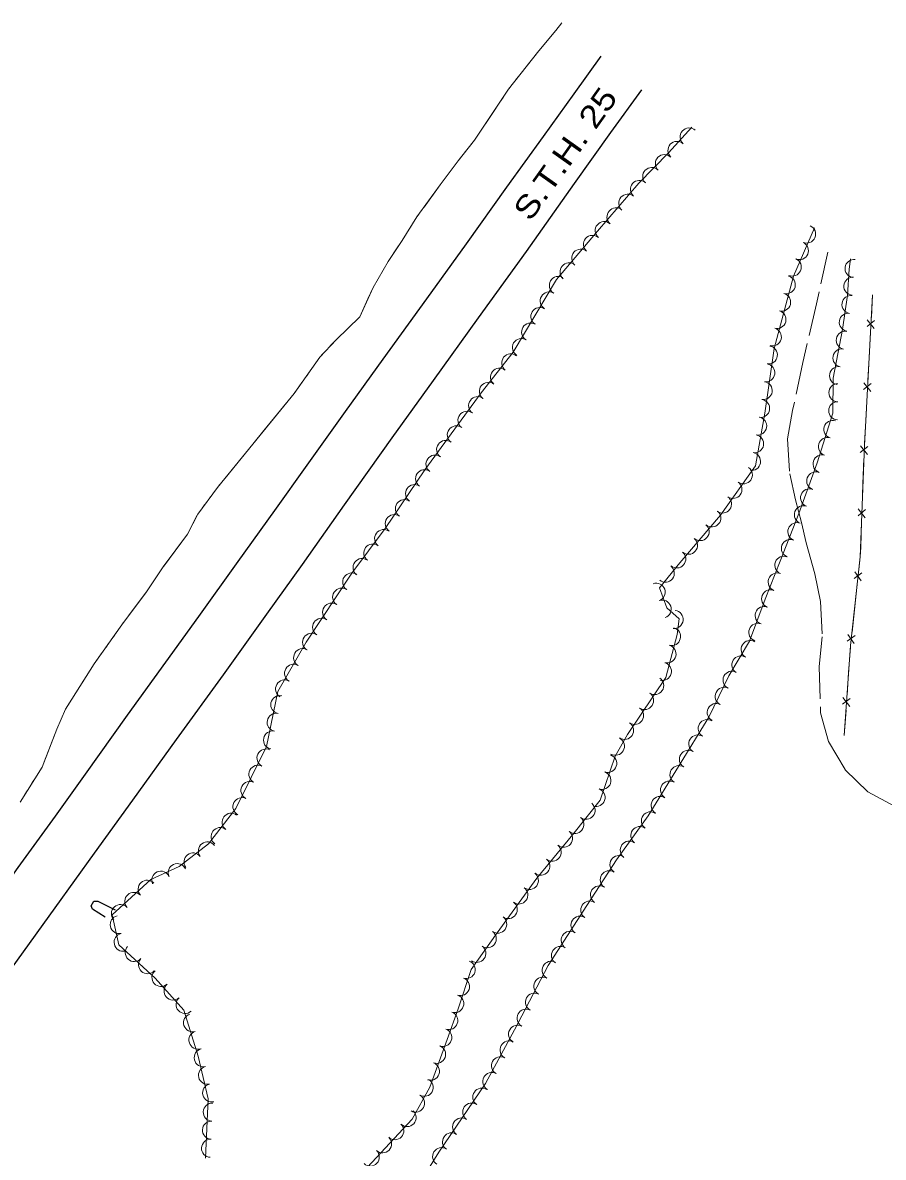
# Model space of a CAD drawing. Extents: x 298761 to 300931, y 48584 to 50968.
# Drawn here: x 300012 to 300394, y 49634 to 50137 of the extents above; entities that cross this region are included whole.
import ezdxf

# ---------------------------------------------------------------- set-up
doc = ezdxf.new("R2010")
doc.units = 0
doc.header["$LTSCALE"] = 2.4
doc.linetypes.add('LONG_DASHED', pattern=[7.5, 6, -1.5])
for name, color, linetype, lineweight in [('11', 7, 'Continuous', 25), ('15', 7, 'Continuous', 13), ('17', 7, 'LONG_DASHED', 13), ('18', 7, 'Continuous', 13), ('19', 7, 'Continuous', 13)]:
    doc.layers.add(name, color=color, linetype=linetype, lineweight=lineweight)

msp = doc.modelspace()

# ---------------------------------------------------------------- linework, layer by layer
at = {"layer": '11'}
for points in [[(299915.873, 49630.321), (299931.973, 49652.924), (299946.639, 49673.137), (299961.48, 49693.774), (299977.848, 49716.32), (299993.395, 49737.881), (300010.454, 49762.179), (300027.109, 49784.923), (300040.39, 49803.549), (300059.076, 49829.713), (300075.951, 49853.169), (300090.619, 49873.467), (300108.059, 49897.84), (300124.331, 49920.482), (300138.8, 49940.607), (300155.789, 49964.508), (300172.496, 49987.622), (300191.823, 50014.425), (300209.423, 50038.876), (300227.388, 50064), (300243.582, 50086.409), (300257.176, 50105.425), (300269.259, 50122.088)], [(299941.753, 49625.456), (299958.193, 49648.483), (299975.851, 49673.327), (299990.952, 49694.469), (300010.158, 49721.046), (300026.858, 49744.237), (300044.29, 49768.502), (300061.337, 49792.04), (300080.812, 49818.961), (300101.569, 49847.571), (300120.862, 49874.589), (300136.668, 49896.558), (300155.344, 49923.099), (300176.493, 49952.718), (300194.769, 49978.148), (300214.8, 50006.036), (300236.015, 50035.498), (300257.333, 50065.558), (300273.546, 50088.222), (300287.176, 50107.164)]]:
    msp.add_lwpolyline(points, dxfattribs=at)
at = {"layer": '15'}
for p, q in [((300389.671, 50016.169), (300389.121, 50006.178)), ((300390.552, 50004.76), (300387.216, 50002.13)), ((300387.312, 50005.11), (300390.356, 50001.201)), ((300388.757, 49999.573), (300388.131, 49988.213)), ((300388.131, 49988.213), (300387.581, 49978.222)), ((300389.012, 49976.804), (300385.676, 49974.174)), ((300385.772, 49977.154), (300388.816, 49973.245)), ((300387.217, 49971.617), (300386.591, 49960.257)), ((300386.591, 49960.257), (300386.041, 49950.265)), ((300387.482, 49948.876), (300384.196, 49946.183)), ((300384.235, 49949.164), (300387.353, 49945.314)), ((300385.785, 49943.656), (300385.374, 49932.286)), ((300385.374, 49932.286), (300385.013, 49922.286)), ((300386.472, 49920.896), (300383.186, 49918.203)), ((300383.225, 49921.184), (300386.343, 49917.334)), ((300384.775, 49915.676), (300384.364, 49904.306)), ((300384.935, 49892.843), (300381.46, 49890.399)), ((300381.718, 49893.369), (300384.545, 49889.3)), ((300382.859, 49887.761), (300381.613, 49876.453)), ((300381.613, 49876.453), (300380.518, 49866.506)), ((300381.87, 49865.013), (300378.394, 49862.568)), ((300378.653, 49865.539), (300381.479, 49861.469)), ((300379.823, 49859.929), (300379.024, 49848.579)), ((300379.024, 49848.579), (300378.322, 49838.598)), ((300379.731, 49837.158), (300376.355, 49834.579)), ((300376.496, 49837.557), (300379.481, 49833.603)), ((300377.857, 49831.999), (300377.058, 49820.65))]:
    msp.add_line(p, q, dxfattribs=at)
for points in [[(300389.671, 50016.169), (300385.99, 49949.34), (300384.21, 49900.028), (300379.877, 49860.69), (300377.058, 49820.65)], [(300384.364, 49904.306), (300384.21, 49900.028), (300383.583, 49894.336)]]:
    msp.add_lwpolyline(points, dxfattribs=at)
at = {"layer": '15', "lineweight": 25}
msp.add_lwpolyline([(300049.023, 49740.056), (300043.542, 49743.588), (300042.856, 49745.046), (300044.061, 49747.217), (300045.787, 49747.252), (300053.477, 49743.347)], dxfattribs=at)
at = {"layer": '17'}
msp.add_lwpolyline([(300369.814, 50035.168), (300364.756, 50012.154), (300358.644, 49986.171), (300354.157, 49964.909), (300351.93, 49952.354), (300352.862, 49936.782), (300355.481, 49925.245), (300358.065, 49915.224), (300360.216, 49906.221), (300364.02, 49892.477), (300366.509, 49880.214), (300367.321, 49864.486), (300365.9, 49851.358), (300366.608, 49830.782), (300370.074, 49817.96), (300377.537, 49805.409), (300387.552, 49795.705), (300399.427, 49789.276)], dxfattribs=at)
at = {"layer": '18'}
for points in [[(300309.365, 50090.624), (300299.093, 50079.267), (300285.883, 50065.817), (300267.604, 50044.469), (300249.364, 50023.075), (300230.189, 49990.791), (300215.945, 49972.7), (300190.969, 49938.493), (300173.408, 49912.554), (300158.559, 49892.652), (300138.266, 49862.134), (300125.677, 49840.252), (300120.64, 49815.822), (300107.052, 49788.341), (300094.985, 49772.563), (300081.962, 49762.519), (300069.393, 49756.812), (300052.207, 49741.183), (300055.191, 49727.797), (300071.278, 49713.092), (300083.946, 49698.897), (300090.324, 49678.35), (300094.809, 49659.56), (300093.576, 49633.19)], [(300163.44, 49627.017), (300185.295, 49650.471), (300193.136, 49664.696), (300200.838, 49685.816), (300205.679, 49699.414), (300211.557, 49716.937), (300223.1, 49733.148), (300240.641, 49757.32), (300256.616, 49776.705), (300268.783, 49792.028), (300275.441, 49811.555), (300280.942, 49821.153), (300297.85, 49846.392), (300302.87, 49865.544), (300303.742, 49872.52), (300298.286, 49877.407), (300295.152, 49886.238), (300304.086, 49897.35), (300322.145, 49918.485), (300337.716, 49940.311), (300341.778, 49963.674), (300345.943, 49992.328), (300354.533, 50024.419), (300363.891, 50045.956)], [(300379.907, 50032.105), (300379.256, 50027.523), (300378.522, 50015.988), (300376.24, 50000.754), (300372.223, 49979.264), (300372.056, 49963.768), (300365.108, 49941.606), (300356.899, 49919.176), (300348.706, 49897.989), (300342.018, 49881.127), (300335.004, 49862.502), (300325.862, 49847.101), (300316.916, 49828.823), (300290.109, 49785.104), (300276.001, 49765.599), (300262.894, 49745.199), (300245.75, 49718.677), (300230.794, 49690.164), (300217.846, 49666.333), (300197.106, 49635.767), (300185.784, 49617.543)]]:
    msp.add_lwpolyline(points, dxfattribs=at)
for centre, radius, start, end in [((300308.231, 50086.24), 4.012, 47.87945, 227.86413), ((300302.849, 50080.29), 4.012, 47.87945, 227.86413), ((300297.266, 50074.41), 4.012, 45.52344, 225.50812), ((300291.644, 50068.686), 4.012, 45.52344, 225.50812), ((300286.217, 50062.978), 4.012, 49.43622, 229.4209), ((300280.999, 50056.884), 4.012, 49.43622, 229.4209), ((300275.781, 50050.79), 4.012, 49.43622, 229.4209), ((300270.562, 50044.696), 4.012, 49.43622, 229.4209), ((300360.385, 50043.129), 3.991, 246.52233, 66.50701), ((300265.357, 50038.597), 4.012, 49.55756, 229.54224), ((300357.205, 50035.809), 3.991, 246.52233, 66.50701), ((300260.151, 50032.491), 4.012, 49.55756, 229.54224), ((300254.946, 50026.386), 4.012, 49.55756, 229.54224), ((300354.024, 50028.489), 3.991, 246.52233, 66.50701), ((300381.415, 50027.855), 3.996, 81.92133, 261.90601), ((300250.208, 50020.385), 4.012, 59.29957, 239.28425), ((300351.364, 50020.66), 3.991, 255.02225, 75.00693), ((300380.876, 50020.047), 3.996, 86.3667, 266.35138), ((300246.111, 50013.486), 4.012, 59.29957, 239.28425), ((300349.301, 50012.95), 3.991, 255.02225, 75.00693), ((300380.029, 50011.93), 3.996, 81.4883, 261.47298), ((300242.014, 50006.588), 4.012, 59.29957, 239.28425), ((300347.237, 50005.241), 3.991, 255.02225, 75.00693), ((300237.917, 49999.69), 4.012, 59.29957, 239.28425), ((300378.845, 50004.027), 3.996, 81.4883, 261.47298), ((300345.174, 49997.531), 3.991, 255.02225, 75.00693), ((300377.493, 49996.076), 3.996, 79.41988, 259.40456), ((300233.82, 49992.792), 4.012, 59.29957, 239.28425), ((300343.422, 49989.508), 3.991, 261.73736, 81.72204), ((300229.087, 49985.997), 4.012, 51.79243, 231.77711), ((300376.025, 49988.222), 3.996, 79.41988, 259.40456), ((300224.124, 49979.693), 4.012, 51.79243, 231.77711), ((300342.274, 49981.61), 3.991, 261.73736, 81.72204), ((300374.557, 49980.368), 3.996, 79.41988, 259.40456), ((300219.161, 49973.39), 4.012, 51.79243, 231.77711), ((300341.126, 49973.712), 3.991, 261.73736, 81.72204), ((300374.244, 49972.765), 3.996, 89.39021, 269.37489), ((300214.402, 49967.026), 4.012, 53.87288, 233.85755), ((300339.978, 49965.814), 3.991, 261.73736, 81.72204), ((300374.158, 49964.775), 3.996, 89.39021, 269.37489), ((300209.671, 49960.547), 4.012, 53.87288, 233.85755), ((300204.94, 49954.067), 4.012, 53.87288, 233.85755), ((300338.671, 49958), 3.991, 260.14454, 80.12922), ((300371.969, 49956.5), 3.996, 72.60095, 252.58563), ((300337.304, 49950.137), 3.991, 260.14454, 80.12922), ((300200.209, 49947.587), 4.012, 53.87288, 233.85755), ((300369.579, 49948.875), 3.996, 72.60095, 252.58563), ((300195.478, 49941.107), 4.012, 53.87288, 233.85755), ((300335.937, 49942.274), 3.991, 260.14454, 80.12922), ((300367.188, 49941.251), 3.996, 72.60095, 252.58563), ((300190.884, 49934.622), 4.012, 55.90921, 235.89389), ((300332.327, 49936.354), 3.991, 234.50302, 54.4877), ((300327.692, 49929.857), 3.991, 234.50302, 54.4877), ((300364.423, 49933.65), 3.996, 69.90589, 249.89057), ((300186.386, 49927.979), 4.012, 55.90921, 235.89389), ((300361.677, 49926.146), 3.996, 69.90589, 249.89057), ((300181.889, 49921.335), 4.012, 55.90921, 235.89389), ((300323.057, 49923.36), 3.991, 234.50302, 54.4877), ((300177.391, 49914.691), 4.012, 55.90921, 235.89389), ((300318.294, 49917.194), 3.991, 229.49512, 49.47979), ((300358.931, 49918.642), 3.996, 69.90589, 249.89057), ((300313.11, 49911.126), 3.991, 229.49512, 49.47979), ((300356.039, 49911.152), 3.996, 68.86621, 248.85088), ((300172.687, 49908.076), 4.012, 53.28083, 233.2655), ((300307.925, 49905.059), 3.991, 229.49512, 49.47979), ((300353.157, 49903.7), 3.996, 68.86621, 248.85088), ((300167.889, 49901.645), 4.012, 53.28083, 233.2655), ((300163.091, 49895.215), 4.012, 53.28083, 233.2655), ((300302.741, 49898.991), 3.991, 229.49512, 49.47979), ((300350.26, 49896.234), 3.996, 68.37283, 248.3575), ((300158.503, 49888.776), 4.012, 56.38567, 236.37035), ((300297.692, 49892.73), 3.991, 231.20853, 51.19321), ((300347.314, 49888.806), 3.996, 68.37283, 248.3575), ((300293.628, 49884.286), 3.991, 289.54673, 109.53141), ((300154.061, 49882.095), 4.012, 56.38567, 236.37035), ((300344.368, 49881.378), 3.996, 68.37283, 248.3575), ((300149.618, 49875.414), 4.012, 56.38567, 236.37035), ((300296.297, 49876.765), 3.991, 289.54673, 109.53141), ((300341.547, 49873.941), 3.996, 69.37176, 249.35644), ((300145.176, 49868.733), 4.012, 56.38567, 236.37035), ((300301.595, 49872.187), 3.991, 262.88264, 82.86732), ((300300.457, 49864.577), 3.991, 255.32007, 75.30475), ((300338.731, 49866.464), 3.996, 69.37176, 249.35644), ((300140.733, 49862.052), 4.012, 56.38567, 236.37035), ((300335.286, 49858.881), 3.996, 59.31439, 239.29906), ((300136.732, 49855.258), 4.012, 60.09528, 240.07996), ((300298.434, 49856.857), 3.991, 255.32007, 75.30475), ((300132.732, 49848.303), 4.012, 60.09528, 240.07996), ((300296.41, 49849.137), 3.991, 255.32007, 75.30475), ((300331.208, 49852.01), 3.996, 59.31439, 239.29906), ((300327.283, 49845.247), 3.996, 63.92865, 243.91333), ((300128.731, 49841.349), 4.012, 60.09528, 240.07996), ((300292.947, 49842.827), 3.991, 236.18891, 56.17359), ((300126.613, 49834.393), 4.012, 78.35762, 258.34229), ((300288.505, 49836.196), 3.991, 236.18891, 56.17359), ((300323.77, 49838.07), 3.996, 63.92865, 243.91333), ((300284.063, 49829.565), 3.991, 236.18891, 56.17359), ((300320.257, 49830.893), 3.996, 63.92865, 243.91333), ((300124.993, 49826.535), 4.012, 78.35762, 258.34229), ((300316.262, 49823.755), 3.996, 58.49246, 238.47713), ((300123.373, 49818.677), 4.012, 78.35762, 258.34229), ((300279.622, 49822.935), 3.991, 236.18891, 56.17359), ((300275.532, 49815.914), 3.991, 240.18891, 60.17358), ((300312.085, 49816.943), 3.996, 58.49246, 238.47713), ((300120.45, 49810.701), 4.012, 63.69754, 243.68221), ((300272.123, 49808.298), 3.991, 251.18014, 71.16482), ((300307.908, 49810.131), 3.996, 58.49246, 238.47713), ((300116.894, 49803.509), 4.012, 63.69754, 243.68221), ((300303.731, 49803.319), 3.996, 58.49246, 238.47713), ((300269.548, 49800.744), 3.991, 251.18014, 71.16482), ((300113.338, 49796.317), 4.012, 63.69754, 243.68221), ((300266.972, 49793.19), 3.991, 251.18014, 71.16482), ((300299.554, 49796.507), 3.996, 58.49246, 238.47713), ((300109.782, 49789.125), 4.012, 63.69754, 243.68221), ((300295.377, 49789.695), 3.996, 58.49246, 238.47713), ((300262.505, 49787.48), 3.991, 231.55685, 51.54153), ((300291.028, 49782.807), 3.996, 54.12938, 234.11406), ((300105.008, 49782.212), 4.012, 52.59894, 232.58361), ((300257.542, 49781.23), 3.991, 231.55685, 51.54153), ((300100.134, 49775.839), 4.012, 52.59894, 232.58361), ((300252.548, 49775.054), 3.991, 230.51604, 50.50072), ((300286.345, 49776.332), 3.996, 54.12938, 234.11406), ((300094.452, 49769.5), 4.012, 37.6489, 217.63358), ((300247.473, 49768.895), 3.991, 230.51604, 50.50072), ((300281.662, 49769.858), 3.996, 54.12938, 234.11406), ((300088.098, 49764.6), 4.012, 37.6489, 217.63358), ((300277.1, 49763.441), 3.996, 57.28692, 237.27159), ((300081.106, 49759.824), 4.012, 24.42826, 204.41294), ((300242.397, 49762.736), 3.991, 230.51604, 50.50072), ((300073.801, 49756.507), 4.012, 24.42826, 204.41294), ((300237.374, 49756.374), 3.991, 234.04023, 54.02491), ((300272.781, 49756.718), 3.996, 57.28692, 237.27159), ((300067.746, 49752.476), 4.012, 42.29114, 222.27582), ((300232.686, 49749.915), 3.991, 234.04023, 54.02491), ((300268.461, 49749.995), 3.996, 57.28692, 237.27159), ((300061.811, 49747.078), 4.012, 42.29114, 222.27582), ((300227.999, 49743.455), 3.991, 234.04023, 54.02491), ((300264.137, 49743.269), 3.996, 57.12876, 237.11344), ((300055.875, 49741.68), 4.012, 42.29114, 222.27582), ((300055.339, 49736.784), 4.012, 102.57453, 282.55921), ((300223.311, 49736.996), 3.991, 234.04023, 54.02491), ((300259.799, 49736.559), 3.996, 57.12876, 237.11344), ((300057.085, 49728.953), 4.012, 102.57453, 282.55921), ((300218.648, 49730.496), 3.991, 234.55499, 54.53967), ((300255.461, 49729.848), 3.996, 57.12876, 237.11344), ((300062.001, 49724.417), 4.012, 137.57748, 317.56215), ((300214.018, 49723.995), 3.991, 234.55499, 54.53967), ((300251.124, 49723.138), 3.996, 57.12876, 237.11344), ((300067.922, 49719.004), 4.012, 137.57748, 317.56215), ((300073.882, 49713.328), 4.012, 131.75424, 311.73892), ((300209.321, 49716.839), 3.991, 251.4639, 71.44858), ((300246.985, 49716.53), 3.996, 62.32918, 242.31386), ((300206.783, 49709.273), 3.991, 251.4639, 71.44858), ((300243.274, 49709.454), 3.996, 62.32918, 242.31386), ((300079.224, 49707.342), 4.012, 131.75424, 311.73892), ((300239.562, 49702.378), 3.996, 62.32918, 242.31386), ((300084.566, 49701.356), 4.012, 131.75424, 311.73892), ((300204.245, 49701.706), 3.991, 251.4639, 71.44858), ((300087.908, 49693.215), 4.012, 107.25254, 287.23722), ((300201.61, 49694.214), 3.991, 250.41151, 70.39619), ((300235.85, 49695.302), 3.996, 62.32918, 242.31386), ((300232.11, 49688.206), 3.996, 61.49128, 241.47596), ((300090.287, 49685.553), 4.012, 107.25254, 287.23722), ((300198.934, 49686.695), 3.991, 250.41151, 70.39619), ((300092.63, 49677.735), 4.012, 103.43245, 283.41712), ((300196.206, 49679.212), 3.991, 249.97186, 69.95654), ((300228.295, 49681.185), 3.996, 61.49128, 241.47596), ((300224.481, 49674.164), 3.996, 61.49128, 241.47596), ((300094.492, 49669.932), 4.012, 103.43245, 283.41712), ((300193.472, 49671.714), 3.991, 249.97186, 69.95654), ((300220.666, 49667.143), 3.996, 61.49128, 241.47596), ((300096.355, 49662.128), 4.012, 103.43245, 283.41712), ((300190.692, 49664.59), 3.991, 241.14355, 61.12823), ((300186.84, 49657.6), 3.991, 241.14355, 61.12823), ((300216.245, 49660.249), 3.996, 55.84952, 235.8342), ((300096.632, 49653.584), 4.012, 87.33059, 267.31527), ((300211.759, 49653.637), 3.996, 55.84952, 235.8342), ((300183.091, 49651.169), 3.991, 227.02885, 47.01352), ((300207.272, 49647.025), 3.996, 55.84952, 235.8342), ((300096.257, 49645.57), 4.012, 87.33059, 267.31527), ((300177.65, 49645.33), 3.991, 227.02885, 47.01352), ((300095.882, 49637.555), 4.012, 87.33059, 267.31527), ((300172.209, 49639.492), 3.991, 227.02885, 47.01352), ((300202.786, 49640.413), 3.996, 55.84952, 235.8342), ((300166.768, 49633.653), 3.991, 227.02885, 47.01352), ((300198.377, 49633.851), 3.996, 58.15627, 238.14095)]:
    msp.add_arc(centre, radius, start, end, dxfattribs=at)
at = {"layer": '19'}
for p, q in [((300231.234, 50111.378), (300232.39, 50112.856)), ((300224.676, 50102.239), (300225.718, 50103.799)), ((300184.331, 50045.809), (300185.325, 50047.398)), ((300181.35, 50041.043), (300182.344, 50042.632)), ((300145.137, 49989.438), (300146.412, 49990.806)), ((300141.791, 49984.939), (300142.865, 49986.473)), ((300138.566, 49980.338), (300139.641, 49981.872)), ((300092.12, 49921.52), (300093.235, 49923.025)), ((300095.465, 49926.036), (300096.581, 49927.541)), ((300052.744, 49864.531), (300053.827, 49866.063)), ((300049.496, 49859.934), (300050.579, 49861.466)), ((300019.446, 49804.035), (300020.439, 49805.627)), ((300016.467, 49799.26), (300017.46, 49800.852)), ((300013.487, 49794.485), (300014.48, 49796.077))]:
    msp.add_line(p, q, dxfattribs=at)
for points in [[(300011.41, 49791.155), (300021.077, 49806.65), (300027.679, 49823.429), (300031.493, 49832.338), (300044.224, 49852.472), (300056.442, 49869.764), (300067.379, 49884.449), (300074.896, 49895.455), (300085.64, 49910.049), (300090.196, 49918.924), (300098.941, 49930.726), (300114.578, 49949.979), (300132.997, 49972.391), (300144.357, 49988.601), (300151.533, 49996.302), (300162.156, 50006.491), (300167.991, 50019.527), (300174.699, 50031.066), (300180.894, 50040.315), (300187.429, 50050.76), (300197.717, 50065.028), (300205.772, 50075.619), (300213.018, 50084.802), (300228.135, 50107.414), (300241.483, 50124.484), (300249.045, 50133.542), (300251.814, 50136.948)], [(300234.701, 50115.811), (300241.483, 50124.484), (300249.045, 50133.542), (300251.814, 50136.948)], [(300227.803, 50106.918), (300228.135, 50107.414), (300228.923, 50108.422)], [(300206.839, 50076.971), (300213.018, 50084.802), (300222.59, 50099.12)], [(300190.594, 50055.149), (300197.717, 50065.028), (300205.772, 50075.619), (300206.839, 50076.971)], [(300187.313, 50050.575), (300187.429, 50050.76), (300188.399, 50052.105)], [(300165.705, 50014.42), (300167.991, 50019.527), (300174.699, 50031.066), (300179.289, 50037.918)], [(300148.961, 49993.542), (300151.533, 49996.302), (300162.156, 50006.491), (300165.705, 50014.42)], [(300119.521, 49955.993), (300132.997, 49972.391), (300136.417, 49977.271)], [(300102.349, 49934.922), (300114.578, 49949.979), (300119.521, 49955.993)], [(300098.811, 49930.551), (300098.941, 49930.726), (300099.985, 49932.012)], [(300075.127, 49895.768), (300085.64, 49910.049), (300089.96, 49918.465)], [(300059.337, 49873.651), (300067.379, 49884.449), (300074.896, 49895.455), (300075.127, 49895.768)], [(300055.992, 49869.128), (300056.442, 49869.764), (300057.097, 49870.644)], [(300032.566, 49834.036), (300044.224, 49852.472), (300047.331, 49856.869)], [(300022.009, 49809.019), (300027.679, 49823.429), (300031.493, 49832.338), (300032.566, 49834.036)]]:
    msp.add_lwpolyline(points, dxfattribs=at)

# ---------------------------------------------------------------- texts
at = {"layer": '11', "width": 1.2}
msp.add_text('S.T.H. 25', height=10, rotation=54.656, dxfattribs=at).set_placement((300237.751, 50048.318))

doc.saveas('drawing.dxf')
